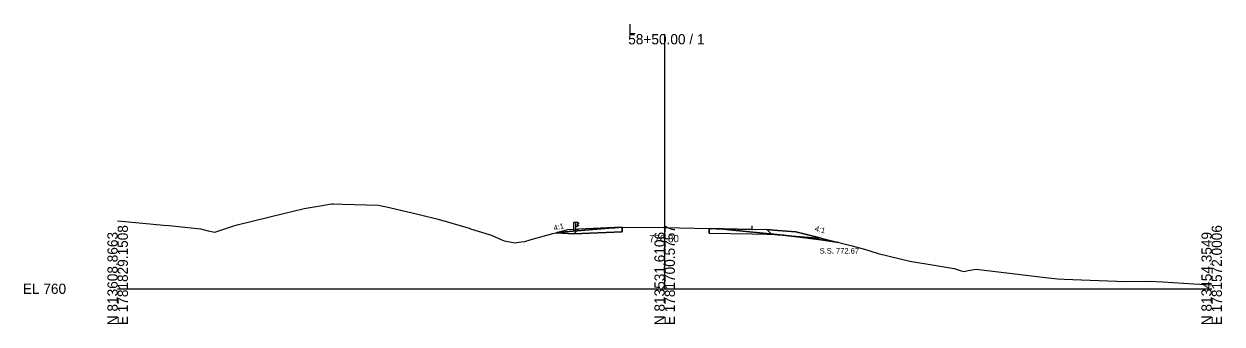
# Model space of a CAD drawing. Extents: x -26 to 7903, y -10 to 9573.
# Drawn here: x 1974.3 to 2302.8, y 9490.3 to 9572.7 of the extents above; entities that cross this region are included whole.
import ezdxf

# ---------------------------------------------------------------- set-up
doc = ezdxf.new("R2010")
doc.units = 0
for name, color, linetype in [('Exist Cross Section Cell', 7, 'Continuous'), ('Exist XS Center Line Elevation Label', 7, 'Continuous'), ('Exist XS Ground Line', 7, 'Continuous'), ('Prop XS Ditch Slope Text', 7, 'Continuous'), ('Prop XS Dump Level', 7, 'Continuous'), ('Prop XS Earthwork Shape', 7, 'Continuous'), ('Prop XS EOT Tick Mark', 7, 'Continuous'), ('Prop XS Finish Grade', 7, 'Continuous'), ('Prop XS Finish Grade Earthwork', 7, 'Continuous'), ('Prop XS Finish Grade Paved Shoulder', 7, 'Continuous'), ('Prop XS Finish Grade Pavement', 7, 'Continuous'), ('Prop XS Guardrail', 7, 'Continuous'), ('Prop XS Hydro Fill Slope Data', 7, 'Continuous'), ('Prop XS Pvmt Edge Slope', 7, 'Continuous'), ('Prop XS Side Slope Text', 7, 'Continuous'), ('Prop XS SS Elevation Text', 7, 'Continuous'), ('Prop XS Subgrade Earthwork', 7, 'Continuous'), ('Scratch_Level_3', 7, 'Continuous'), ('Scratch_Level_6', 7, 'Continuous')]:
    doc.layers.add(name, color=color, linetype=linetype)

msp = doc.modelspace()

# ---------------------------------------------------------------- linework, layer by layer
at = {"layer": 'Exist Cross Section Cell'}
for p, q in [((2150, 9500), (2150, 9569.94)), ((2000, 9500), (2150, 9500)), ((2150, 9500), (2300, 9500))]:
    msp.add_line(p, q, dxfattribs=at)
at = {"layer": 'Exist XS Ground Line'}
for p, q in [((2045.83, 9520.74), (2048.11, 9521.31)), ((2048.11, 9521.31), (2051.18, 9522.02)), ((2051.18, 9522.02), (2055.49, 9522.77)), ((2055.49, 9522.77), (2058.64, 9523.29)), ((2058.64, 9523.29), (2059.23, 9523.31)), ((2059.23, 9523.31), (2061.7, 9523.22)), ((2061.7, 9523.22), (2071.51, 9522.99)), ((2071.51, 9522.99), (2074.55, 9522.35)), ((2074.55, 9522.35), (2082.65, 9520.4)), ((2000, 9518.62), (2006.86, 9518.03)), ((2006.86, 9518.03), (2012.55, 9517.45)), ((2032.79, 9517.57), (2045.83, 9520.74)), ((2082.65, 9520.4), (2087.87, 9519.11)), ((2087.87, 9519.11), (2095.51, 9516.88)), ((2012.55, 9517.45), (2014.08, 9517.37)), ((2014.08, 9517.37), (2016.66, 9517.13)), ((2016.66, 9517.13), (2022.76, 9516.5)), ((2022.76, 9516.5), (2024.79, 9515.89)), ((2024.79, 9515.89), (2026.67, 9515.54)), ((2026.67, 9515.54), (2029.96, 9516.63)), ((2029.96, 9516.63), (2031.6, 9517.19)), ((2031.6, 9517.19), (2032.79, 9517.57)), ((2095.51, 9516.88), (2096.42, 9516.63)), ((2096.42, 9516.63), (2096.8, 9516.51)), ((2096.8, 9516.51), (2101.89, 9514.91)), ((2101.89, 9514.91), (2102.23, 9514.78)), ((2102.23, 9514.78), (2105.99, 9513.19)), ((2113.4, 9513.55), (2119.36, 9515.17)), ((2119.36, 9515.17), (2120.24, 9515.39)), ((2120.24, 9515.39), (2120.54, 9515.42)), ((2120.54, 9515.42), (2134.66, 9516.68)), ((2134.66, 9516.68), (2136.34, 9516.77)), ((2136.34, 9516.77), (2138.37, 9516.88)), ((2138.37, 9516.88), (2149.7, 9516.81)), ((2149.7, 9516.81), (2150, 9516.8)), ((2150, 9516.8), (2162.17, 9516.56)), ((2162.17, 9516.56), (2166.09, 9516.39)), ((2166.09, 9516.39), (2167.71, 9516.23)), ((2167.71, 9516.23), (2180.76, 9514.93)), ((2180.76, 9514.93), (2186.38, 9514.24)), ((2105.99, 9513.19), (2108.51, 9512.7)), ((2108.51, 9512.7), (2108.9, 9512.63)), ((2108.9, 9512.63), (2110.66, 9512.89)), ((2110.66, 9512.89), (2111.64, 9513.03)), ((2111.64, 9513.03), (2113.4, 9513.55)), ((2186.38, 9514.24), (2192.87, 9513.42)), ((2192.87, 9513.42), (2197.75, 9512.67)), ((2197.75, 9512.67), (2201.41, 9511.79)), ((2201.41, 9511.79), (2204.81, 9510.84)), ((2204.81, 9510.84), (2208.57, 9509.7)), ((2208.57, 9509.7), (2217.27, 9507.62)), ((2217.27, 9507.62), (2224.42, 9506.43)), ((2224.42, 9506.43), (2225.57, 9506.25)), ((2225.57, 9506.25), (2229.4, 9505.53)), ((2229.4, 9505.53), (2231.35, 9504.94)), ((2231.35, 9504.94), (2232.16, 9504.74)), ((2232.16, 9504.74), (2233.19, 9504.98)), ((2233.19, 9504.98), (2235.38, 9505.41)), ((2235.38, 9505.41), (2254.42, 9503.12)), ((2254.42, 9503.12), (2257.69, 9502.7)), ((2257.69, 9502.7), (2259.57, 9502.68)), ((2259.57, 9502.68), (2276.32, 9501.99)), ((2276.32, 9501.99), (2283.06, 9502.11)), ((2283.06, 9502.11), (2286.59, 9501.89)), ((2286.59, 9501.89), (2295.09, 9501.33)), ((2295.09, 9501.33), (2300, 9501.08))]:
    msp.add_line(p, q, dxfattribs=at)
at = {"layer": 'Prop XS Dump Level'}
for p, q in [((2162.18, 9516.56), (2174, 9516.32)), ((2174, 9516.32), (2162.18, 9516.56))]:
    msp.add_line(p, q, dxfattribs=at)
at = {"layer": 'Prop XS Earthwork Shape'}
for points in [[(2138.37, 9515.63), (2138.37, 9516.88), (2136.34, 9516.77), (2134.66, 9516.68), (2120.54, 9515.42), (2120.24, 9515.39), (2125.07, 9515.1)], [(2181, 9514.84), (2182.55, 9514.71), (2180.76, 9514.93), (2167.71, 9516.23), (2166.09, 9516.39), (2162.17, 9516.56), (2162.17, 9515.31), (2174, 9515.08), (2178, 9515), (2179.28, 9514.97)], [(2186, 9514.44), (2192.9, 9513.88), (2197.74, 9512.67), (2192.87, 9513.42), (2186.38, 9514.24), (2182.55, 9514.71)]]:
    msp.add_lwpolyline(points, close=True, dxfattribs=at)
at = {"layer": 'Prop XS EOT Tick Mark'}
msp.add_line((2174, 9516.33), (2174, 9517.33), dxfattribs=at)
at = {"layer": 'Prop XS Finish Grade'}
for p, q in [((2123.37, 9516.16), (2120.24, 9515.39)), ((2126.37, 9516.4), (2123.37, 9516.16)), ((2178, 9516.25), (2181, 9516.01)), ((2181, 9516.01), (2186, 9515.61)), ((2186, 9515.61), (2192.9, 9513.88))]:
    msp.add_line(p, q, dxfattribs=at)
at = {"layer": 'Prop XS Finish Grade Earthwork'}
msp.add_line((2192.9, 9513.88), (2197.74, 9512.67), dxfattribs=at)
at = {"layer": 'Prop XS Finish Grade Paved Shoulder'}
msp.add_line((2174, 9516.33), (2178, 9516.25), dxfattribs=at)
at = {"layer": 'Prop XS Finish Grade Pavement'}
for p, q in [((2138.37, 9516.88), (2126.37, 9516.4)), ((2162.17, 9516.56), (2174, 9516.33))]:
    msp.add_line(p, q, dxfattribs=at)
at = {"layer": 'Prop XS Guardrail'}
for p, q in [((2125.05, 9518.28), (2125.55, 9518.28)), ((2125.05, 9515.78), (2125.05, 9518.28)), ((2125.55, 9518.28), (2126.05, 9518.28)), ((2125.55, 9518.28), (2125.55, 9515.78)), ((2126.05, 9518.28), (2126.34, 9518.08)), ((2126.34, 9517.96), (2126.05, 9517.76)), ((2126.05, 9517.76), (2126.05, 9517.66)), ((2126.05, 9517.66), (2126.34, 9517.46)), ((2126.34, 9518.08), (2126.37, 9518.02)), ((2126.37, 9518.02), (2126.34, 9517.96)), ((2126.05, 9517.14), (2125.55, 9517.14)), ((2126.34, 9517.34), (2126.05, 9517.14)), ((2126.34, 9517.46), (2126.37, 9517.4)), ((2126.37, 9517.4), (2126.34, 9517.34))]:
    msp.add_line(p, q, dxfattribs=at)
at = {"layer": 'Prop XS Hydro Fill Slope Data'}
msp.add_line((2186, 9515.61), (2197.74, 9512.67), dxfattribs=at)
at = {"layer": 'Prop XS Pvmt Edge Slope'}
for p, q in [((2126.37, 9516.4), (2125.07, 9515.1)), ((2178, 9516.25), (2179.28, 9514.97))]:
    msp.add_line(p, q, dxfattribs=at)
at = {"layer": 'Prop XS Subgrade Earthwork'}
for p, q in [((2125.07, 9515.1), (2120.24, 9515.39)), ((2138.37, 9515.63), (2125.07, 9515.1)), ((2138.37, 9515.63), (2138.37, 9516.88)), ((2162.17, 9515.31), (2162.17, 9516.56)), ((2162.17, 9515.31), (2174, 9515.08)), ((2174, 9515.08), (2178, 9515)), ((2178, 9515), (2179.28, 9514.97)), ((2179.28, 9514.97), (2181, 9514.84)), ((2181, 9514.84), (2186, 9514.44)), ((2186, 9514.44), (2192.9, 9513.88))]:
    msp.add_line(p, q, dxfattribs=at)
at = {"layer": 'Scratch_Level_3'}
for p, q in [((2123.37, 9516.16), (2120.24, 9515.39)), ((2120.24, 9515.39), (2125.07, 9515.1)), ((2126.37, 9516.4), (2123.37, 9516.16)), ((2125.07, 9515.1), (2126.37, 9516.4)), ((2181, 9516.01), (2178, 9516.25)), ((2178, 9516.25), (2179.28, 9514.97)), ((2179.28, 9514.97), (2181, 9514.84)), ((2186, 9515.61), (2181, 9516.01)), ((2181, 9514.84), (2186, 9514.44)), ((2192.9, 9513.88), (2186, 9515.61)), ((2186, 9514.44), (2192.9, 9513.88))]:
    msp.add_line(p, q, dxfattribs=at)
at = {"layer": 'Scratch_Level_6'}
for points in [[(2138.37, 9515.63), (2125.07, 9515.1), (2120.24, 9515.39), (2120.54, 9515.42), (2134.66, 9516.68), (2136.34, 9516.77), (2138.37, 9516.88)], [(2179.28, 9514.97), (2181, 9514.84), (2182.55, 9514.71), (2180.76, 9514.93), (2167.71, 9516.23), (2166.09, 9516.39), (2162.17, 9516.56), (2162.17, 9515.31), (2174, 9515.08), (2178, 9515)]]:
    msp.add_lwpolyline(points, close=True, dxfattribs=at)

# ---------------------------------------------------------------- texts
at = {"layer": 'Exist Cross Section Cell'}
for s, p in [('L', (2140, 9569.94)), ('58+50.00 / 1', (2140, 9567.14)), ('EL 760', (1974, 9498.6))]:
    msp.add_text(s, height=2.8, dxfattribs=at).set_placement(p)
for s, p in [('N 813608.8663', (2000, 9490)), ('E 1781829.1508', (2002.8, 9490)), ('N 813531.6106', (2150, 9490)), ('E 1781700.5757', (2152.8, 9490)), ('N 813454.3549', (2300, 9490)), ('E 1781572.0006', (2302.8, 9490))]:
    msp.add_text(s, height=2.8, rotation=90, dxfattribs=at).set_placement(p)
at = {"layer": 'Exist XS Center Line Elevation Label'}
msp.add_text('776.80', height=2, dxfattribs=at).set_placement((2145.71, 9512.8))
at = {"layer": 'Prop XS Ditch Slope Text'}
msp.add_text('4:1', height=1.5, rotation=14.0362, dxfattribs=at).set_placement((2119.72, 9515.93))
at = {"layer": 'Prop XS Dump Level'}
for s, height, p in [('Eop', 0.3, (2162.17, 9516.26)), ('Case4', 0.04, (2186, 9515.57))]:
    msp.add_text(s, height=height, dxfattribs=at).set_placement(p)
at = {"layer": 'Prop XS Side Slope Text'}
msp.add_text('4:1', height=1.5, rotation=345.9638, dxfattribs=at).set_placement((2191.06, 9515.89))
at = {"layer": 'Prop XS SS Elevation Text'}
msp.add_text('S.S. 772.67', height=1.5, dxfattribs=at).set_placement((2192.48, 9509.67))

doc.saveas('drawing.dxf')
